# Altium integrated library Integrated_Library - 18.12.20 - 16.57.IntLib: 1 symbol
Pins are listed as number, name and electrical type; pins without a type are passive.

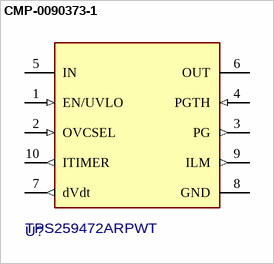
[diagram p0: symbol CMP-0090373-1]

## CMP-0090373-1
designator U?, comment TPS259472ARPWT
2.7- 23V, 5.5 A, 28 mΩ Reverse Current Blocking eFuse with Input Reverse Polarity Protection; Manufacturer: Texas Instruments; Threshold Voltage: 1.2/1.1V; Reset Type: Active Low; AEC Qualified: No; Standoff Height: 0mm; Number Of Outputs: 1; SizeZ_mm: 1mm; Min Supply Voltage: 2.7V; Nominal Supply Current: 450uA; Reset Timeout: 100ms; TJmax_C: +125°C
footprint RPW0010A-MFG
pins: 1 EN/UVLO (in), 2 OVCSEL (in), 3 PG (out), 4 PGTH (in), 5 IN (power), 6 OUT (power), 7 dVdt (out), 8 GND (power), 9 ILM (out), 10 ITIMER (out)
